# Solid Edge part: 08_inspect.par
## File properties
Author: edge
Template: jis part.par
Last saved by: edge
Revision: 3
Application: Solid Edge
文書内容のタイプ: 0
Accuracy: 0.990
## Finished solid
Body 1: sheet body, 2 faces, 5 edges, 4 vertices.
  Faces by surface: spun 2
  Edges by curve: curve on surface 5
Body 2: sheet body, 2 faces, 9 edges, 8 vertices.
  Faces by surface: spline 2
  Edges by curve: curve on surface 9
Body 3: solid body, 36 faces, 82 edges, 48 vertices.
  Faces by surface: blend 11, cylinder 10, plane 10, torus 3, sphere 1, spline 1
  Edges by curve: line 30, circle 29, intersection 22, spline 1
Bounding box of the edges (mm; curved faces can reach further): 52.500 x 32.500 x 68.000, from (0, -32.5, 0) to (52.5, 0, 68).
Cylindrical faces by radius (mm): R3 x2, R5 x3, R7 x3, R10 x1, R20 x1
Toroidal faces (ring radius, tube radius in mm): R8 r3 x1, R15 r5 x1, R17 r10 x1
Spherical faces by radius (mm): R7 x1
Planar faces by outward normal: +x 3, +y 1, +z 2, -x 1, -y 2, -z 1
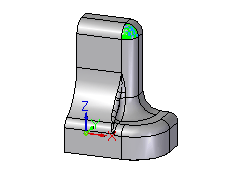
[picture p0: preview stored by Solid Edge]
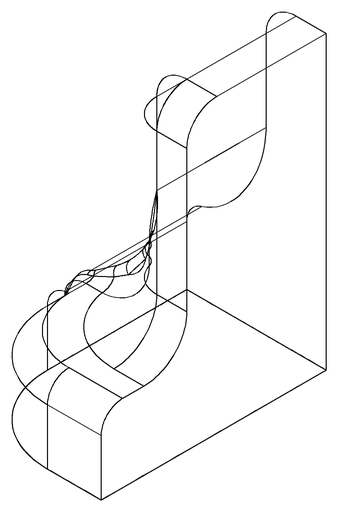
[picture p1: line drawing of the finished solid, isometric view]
